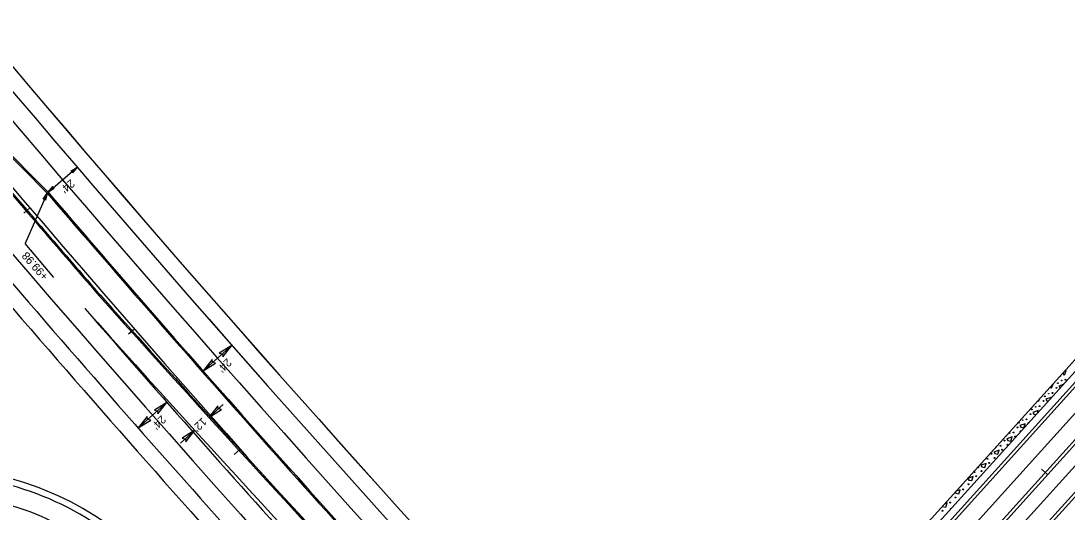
# Model space of a CAD drawing. Extents: x 1262642 to 1268358, y 767825 to 773481.
# Drawn here: x 1266385 to 1267039, y 772413 to 772720 of the extents above; entities that cross this region are included whole.
import ezdxf

# ---------------------------------------------------------------- set-up
doc = ezdxf.new("R2010")
doc.units = 0
for name, color, linetype in [('Default', 7, 'Continuous'), ('Prop Conc 1ft 6in Curb and Gutter', 7, 'Continuous'), ('Prop Conc 2ft 6in Curb and Gutter', 7, 'Continuous'), ('Prop Conc 4in Sidewalk', 7, 'Continuous'), ('Prop Conc 5in Monolithic Keyed In Island', 7, 'Continuous'), ('Prop Dimension', 7, 'Continuous'), ('Prop Dimension Text', 7, 'Continuous'), ('Prop EOT', 7, 'Continuous'), ('Prop Horizontal Alignment', 7, 'Continuous'), ('Prop Horizontal Alignment Tick Small', 7, 'Continuous'), ('Prop Lane Lines', 7, 'Continuous'), ('Prop Paved Shoulder', 7, 'Continuous'), ('Prop Shade Light', 7, 'Continuous'), ('Prop Terminator CELL', 7, 'Continuous')]:
    doc.layers.add(name, color=color, linetype=linetype)

msp = doc.modelspace()

# ---------------------------------------------------------------- linework, layer by layer
at = {"layer": 'Default'}
msp.add_line((1266402.3, 772612.98), (1266420.53, 772628.6), dxfattribs=at)
at = {"layer": 'Prop Conc 1ft 6in Curb and Gutter'}
msp.add_line((1266401.77, 772612.45), (1266295.81, 772719.17), dxfattribs=at)
for centre, radius, start, end in [((1275047.31, 780021.23), 11402.25, 220.298228, 220.945622), ((1275058.64, 780031.06), 11400.75, 220.595039, 220.947952), ((1275047.31, 780021.23), 11385.75, 220.946412, 223.103661), ((1274932.68, 780143.08), 11396.75, 221.786199, 223.669794)]:
    msp.add_arc(centre, radius, start, end, dxfattribs=at)
at = {"layer": 'Prop Conc 2ft 6in Curb and Gutter'}
for p, q in [((1267131.94, 772606.25), (1266835.45, 772278.08)), ((1267135.45, 772602.68), (1266839.16, 772274.72)), ((1267138.61, 772599.46), (1266842.5, 772271.71)), ((1267174.15, 772567.2), (1266880.18, 772241.82)), ((1267036.89, 772498.62), (1267036.21, 772500.29)), ((1267038.02, 772501.26), (1267036.89, 772498.62)), ((1267037.76, 772502.01), (1267038.02, 772501.26)), ((1267028.76, 772490.38), (1267028.3, 772491.53)), ((1267029.89, 772493.02), (1267028.76, 772490.38)), ((1267029.82, 772493.22), (1267029.89, 772493.02)), ((1267036.24, 772492.86), (1267033.59, 772491.97)), ((1267033.59, 772491.97), (1267034.24, 772490.98)), ((1267034.24, 772490.98), (1267034.49, 772490.93)), ((1267021.39, 772483.89), (1267020.64, 772482.13)), ((1267028.84, 772484.86), (1267025.47, 772483.72)), ((1267025.47, 772483.72), (1267026.12, 772482.74)), ((1267028.72, 772484.54), (1267028.84, 772484.86)), ((1267020.64, 772482.13), (1267020.38, 772482.77)), ((1267026.12, 772482.74), (1267026.94, 772482.57)), ((1267012.52, 772473.89), (1267012.47, 772474.01)), ((1267012.66, 772474.22), (1267012.52, 772473.89)), ((1267020.72, 772476.62), (1267017.35, 772475.48)), ((1267017.35, 772475.48), (1267017.99, 772474.49)), ((1267017.99, 772474.49), (1267019.38, 772474.2)), ((1267020.14, 772475.04), (1267020.72, 772476.62)), ((1267012.59, 772468.37), (1267009.22, 772467.23)), ((1267009.22, 772467.23), (1267009.87, 772466.25)), ((1267009.87, 772466.25), (1267011.67, 772465.87)), ((1267011.67, 772465.87), (1267012.59, 772468.37)), ((1267004.47, 772460.13), (1267001.1, 772458.99)), ((1267001.1, 772458.99), (1267001.75, 772458.01)), ((1267001.75, 772458.01), (1267003.55, 772457.63)), ((1267003.55, 772457.63), (1267004.47, 772460.13)), ((1266996.35, 772451.88), (1266992.98, 772450.75)), ((1266995.43, 772449.39), (1266996.35, 772451.88)), ((1266992.98, 772450.75), (1266993.62, 772449.76)), ((1266993.62, 772449.76), (1266995.43, 772449.39)), ((1266988.22, 772443.64), (1266984.85, 772442.5)), ((1266984.85, 772442.5), (1266985.5, 772441.52)), ((1266985.5, 772441.52), (1266987.3, 772441.14)), ((1266987.3, 772441.14), (1266988.22, 772443.64)), ((1266980.1, 772435.4), (1266976.73, 772434.26)), ((1266976.73, 772434.26), (1266977.38, 772433.27)), ((1266977.38, 772433.27), (1266979.18, 772432.9)), ((1266979.18, 772432.9), (1266980.1, 772435.4)), ((1266968.82, 772425.69), (1266969.25, 772425.03)), ((1266969.25, 772425.03), (1266971.06, 772424.65)), ((1266971.98, 772427.15), (1266969.32, 772426.25)), ((1266971.06, 772424.65), (1266971.98, 772427.15)), ((1266963.85, 772418.91), (1266962.17, 772418.34)), ((1266962.93, 772416.41), (1266963.85, 772418.91)), ((1266960.98, 772417.02), (1266961.13, 772416.78)), ((1266961.13, 772416.78), (1266962.93, 772416.41))]:
    msp.add_line(p, q, dxfattribs=at)
for centre, radius in [((1267032.04, 772490.85), 0.268), ((1267032.96, 772493.78), 0.268), ((1267035.35, 772495.44), 0.18), ((1267037.78, 772495.91), 0.268), ((1267024.84, 772485.54), 0.268), ((1267027.22, 772487.2), 0.18), ((1267029.66, 772487.67), 0.268), ((1267016.71, 772477.29), 0.268), ((1267019.1, 772478.95), 0.18), ((1267021.54, 772479.43), 0.268), ((1267023.91, 772482.6), 0.268), ((1267010.98, 772470.71), 0.18), ((1267013.41, 772471.18), 0.268), ((1267015.79, 772474.36), 0.268), ((1267007.67, 772466.11), 0.268), ((1267008.59, 772469.05), 0.268), ((1266999.54, 772457.87), 0.268), ((1267002.85, 772462.46), 0.18), ((1267005.29, 772462.94), 0.268), ((1267006.37, 772460.4), 0.285), ((1266997.17, 772454.69), 0.268), ((1266998.25, 772452.16), 0.285), ((1267001.44, 772455.32), 0.292), ((1266989.04, 772446.45), 0.268), ((1266991.42, 772449.63), 0.268), ((1266993.32, 772447.08), 0.292), ((1266980.92, 772438.2), 0.268), ((1266985.2, 772438.83), 0.292), ((1266990.12, 772443.91), 0.285), ((1266982, 772435.67), 0.285), ((1266973.88, 772427.42), 0.285), ((1266977.08, 772430.59), 0.292), ((1266965.75, 772419.18), 0.285), ((1266968.95, 772422.34), 0.292), ((1266960.83, 772414.1), 0.292)]:
    msp.add_circle(centre, radius, dxfattribs=at)
for centre, radius, start, end in [((1267034.55, 772498.41), 0.268, 222.48489, 53.32276), ((1267014.49, 772468.64), 0.285, 68.53769, 207.26995), ((1267000.47, 772460.8), 0.268, 239.32741, 36.48023), ((1267009.57, 772463.57), 0.292, 16.77956, 259.02808), ((1266994.73, 772454.22), 0.18, 192.11996, 83.68768), ((1266983.3, 772441.38), 0.268, 169.77278, 106.03486), ((1266972.8, 772429.96), 0.268, 207.52387, 68.28378), ((1266965.87, 772415), 0.289, 45.05417, 230.75347)]:
    msp.add_arc(centre, radius, start, end, dxfattribs=at)
at = {"layer": 'Prop Conc 4in Sidewalk'}
for p, q in [((1267131.94, 772606.25), (1266835.45, 772278.08)), ((1267135.45, 772602.68), (1266839.16, 772274.72))]:
    msp.add_line(p, q, dxfattribs=at)
at = {"layer": 'Prop Conc 5in Monolithic Keyed In Island'}
msp.add_arc((1275045.61, 780019.75), 11400, 220.946412, 220.947952, dxfattribs=at)
at = {"layer": 'Prop Dimension'}
for p in [(1266401.75, 772612.47), (1266406.03, 772559.73)]:
    msp.add_line(p, (1266387.98, 772580.91), dxfattribs=at)
at = {"layer": 'Prop Dimension Text'}
for p, q in [((1266517.13, 772517.33), (1266499.11, 772501.48)), ((1266476.59, 772481.66), (1266458.57, 772465.81)), ((1266511.65, 772480.45), (1266502.77, 772472.37)), ((1266493.9, 772464.3), (1266485.02, 772456.22))]:
    msp.add_line(p, q, dxfattribs=at)
at = {"layer": 'Prop EOT'}
for p, q in [((1266402.3, 772612.98), (1266296.36, 772719.68)), ((1267140.02, 772598.03), (1266843.99, 772270.37)), ((1267172.67, 772568.54), (1266878.7, 772243.16))]:
    msp.add_line(p, q, dxfattribs=at)
for centre, radius, start, end in [((1275047.31, 780021.23), 11361, 216.766365, 222.716029), ((1275047.31, 780021.23), 11403, 220.298366, 220.945622), ((1275058.64, 780031.06), 11400, 220.595039, 220.947952), ((1275047.31, 780021.23), 11439, 220.505091, 222.993587), ((1275047.31, 780021.23), 11385, 220.946412, 222.993587), ((1274932.68, 780143.08), 11397.5, 221.785983, 223.669794), ((1266329.2, 772249.67), 187, 43.23333, 84.99155)]:
    msp.add_arc(centre, radius, start, end, dxfattribs=at)
at = {"layer": 'Prop Horizontal Alignment'}
msp.add_line((1266770.94, 772153.71), (1267443.05, 772897.65), dxfattribs=at)
for centre, radius, start, end in [((1275047.31, 780021.23), 11400, 216.766365, 222.993587), ((1266329.2, 772249.67), 175, 43.23333, 125.81667)]:
    msp.add_arc(centre, radius, start, end, dxfattribs=at)
at = {"layer": 'Prop Horizontal Alignment Tick Small'}
for p, q in [((1266390.91, 772603.22), (1266387.12, 772599.96)), ((1266456.32, 772527.57), (1266452.55, 772524.28)), ((1266522.38, 772452.5), (1266518.64, 772449.18)), ((1267026.52, 772436.61), (1267022.81, 772439.96))]:
    msp.add_line(p, q, dxfattribs=at)
at = {"layer": 'Prop Lane Lines'}
for p, q in [((1267148.18, 772590.66), (1266852.15, 772262.99)), ((1267156.34, 772583.29), (1266860.31, 772255.62)), ((1267164.5, 772575.91), (1266868.47, 772248.25))]:
    msp.add_line(p, q, dxfattribs=at)
for centre, radius, start, end in [((1275047.31, 780021.23), 11373, 216.364944, 223.132748), ((1275047.31, 780021.23), 11427, 216.367499, 223.547684), ((1275047.31, 780021.23), 11415, 220.946412, 223.104121), ((1274932.68, 780143.08), 11409.5, 221.786199, 223.669794)]:
    msp.add_arc(centre, radius, start, end, dxfattribs=at)
at = {"layer": 'Prop Paved Shoulder'}
for centre, radius, start, end in [((1275047.31, 780021.23), 11351, 216.766365, 222.716029), ((1275047.31, 780021.23), 11449, 220.505091, 223.202447), ((1266329.2, 772249.67), 191, 43.23333, 84.99155)]:
    msp.add_arc(centre, radius, start, end, dxfattribs=at)
at = {"layer": 'Prop Shade Light'}
for centre, radius, start, end in [((1275047.31, 780021.23), 11351, 216.765763, 222.716029), ((1275047.31, 780021.23), 11361, 216.765886, 222.716029), ((1275047.31, 780021.23), 11439, 220.505091, 222.993587), ((1275047.31, 780021.23), 11449, 220.505091, 223.202447), ((1266329.2, 772249.67), 191, 43.23333, 84.99155), ((1266329.2, 772249.67), 187, 43.23333, 84.99155)]:
    msp.add_arc(centre, radius, start, end, dxfattribs=at)
at = {"layer": 'Prop Terminator CELL'}
for points in [[(1266416.6, 772626.26), (1266420.53, 772628.6), (1266417.61, 772625.04), (1266417.53, 772626.03)], [(1266406.22, 772615.32), (1266402.3, 772612.98), (1266405.22, 772616.53), (1266405.3, 772615.55)], [(1266399.24, 772608.66), (1266401.75, 772612.47), (1266400.67, 772608), (1266400.17, 772608.85)], [(1266511.4, 772510.22), (1266517.13, 772517.33), (1266509.28, 772512.55), (1266511.2, 772512.11)], [(1266504.85, 772508.59), (1266499.11, 772501.48), (1266506.96, 772506.25), (1266505.04, 772506.7)], [(1266470.85, 772474.56), (1266476.59, 772481.66), (1266468.74, 772476.89), (1266470.66, 772476.45)], [(1266508.39, 772479.58), (1266502.77, 772472.37), (1266510.54, 772477.28), (1266508.62, 772477.69)], [(1266464.3, 772472.92), (1266458.57, 772465.81), (1266466.42, 772470.59), (1266464.5, 772471.03)], [(1266488.28, 772457.1), (1266493.9, 772464.3), (1266486.13, 772459.39), (1266488.06, 772458.98)]]:
    msp.add_lwpolyline(points, close=True, dxfattribs=at)

# ---------------------------------------------------------------- texts
at = {"layer": 'Prop Dimension Text'}
for s, rotation, p in [("24'", 217.64384, (1266416.61, 772621.34)), ('+99.98', 131.17534, (1266402.85, 772560.75)), ("24'", 223.49554, (1266514.1, 772509.6)), ("24'", 223.49554, (1266473.08, 772473.97)), ("12'", 223.49554, (1266498.59, 772472.61))]:
    msp.add_text(s, height=5, rotation=rotation, dxfattribs=at).set_placement(p)

doc.saveas('drawing.dxf')
